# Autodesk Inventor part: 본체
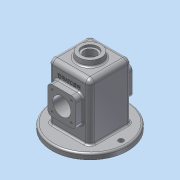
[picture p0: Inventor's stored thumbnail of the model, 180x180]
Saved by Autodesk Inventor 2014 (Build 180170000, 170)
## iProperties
Created: 2021-08
Part Number: 본체
Material: 알루미늄 6061
Document SubType Name: Modeling
Designer: dg
Density: 2.71 g/cm^3
Appearance: 알루미늄 - 평지
Mass: 823.388 g
Surface Area: 950.132 cm^2
Volume: 303.833 cm^3
Author: dg
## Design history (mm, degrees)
sketch "스케치1"
  geometry: L1 (37, -37)-(-37, -37); L2 (-37, -37)-(-37, 37); L3 (-37, 37)-(37, 37); L4 (37, 37)-(37, -37); L5 (37, -37)-(-37, 37); L6 (-37, -37)-(37, 37); 1 further point
  constraints: 12 end point, 2 midpoint, 2 parallel, 1 horizontal, 1 perpendicular
  dimensions: "d0" = 74 distance of L2.end L3.end; "d1" = 74 distance of L3.end L1.start
extrude "돌출1" new body sketch "스케치1" stored distance "d2" = 100; taper "d3" = 0 deg
node "작업 평면1"
sketch "스케치2"
  geometry: C1 r 67 at (0, 0); 1 further point
  constraints: 1 centre point, 1 coincident
  dimensions: "d5" = 134 diameter of C1
extrude "돌출2" join sketch "스케치2" distance "d6" = 10; taper "d7" = 0 deg
sketch "스케치3" dims "d8" = 110
  geometry: L1 (37, -37)-(-37, -37) reference; L2 (0, 0)-(0, 55); C1 r 67 at (0, 0) reference; C2 r 4.5 at (0, 55)
  constraints: 2 coincident, 2 end point, 1 centre point, 1 perpendicular, 1 vertical alignment, 2 other
  dimensions: "d9" = 9 diameter of C2
extrude "돌출3" cut sketch "스케치3" stored distance "d10" = 10; taper "d11" = 0 deg
fillet "모깎기1" dims "d12" = 3
fillet "모깎기2" dims "d13" = 8
sketch "스케치4"
  geometry: C1 r 20 at (0, 0); 1 further point
  constraints: 1 centre point, 1 coincident
  dimensions: "d14" = 40 diameter of C1
extrude "돌출4" join sketch "스케치4" distance "d15" = 10; taper "d16" = 0 deg
sketch "스케치5"
  geometry: L1 (-32, -32)-(32, -32); L2 (32, -32)-(32, 32); L3 (32, 32)-(-32, 32); L4 (-32, 32)-(-32, -32); L5 (-32, -32)-(32, 32); L6 (32, -32)-(-32, 32); C1 r 67 at (0, 0) reference
  constraints: 12 end point, 2 midpoint, 2 parallel, 1 horizontal, 1 perpendicular
  dimensions: "d17" = 64 distance of L2.end L3.end; "d18" = 64 distance of L1.end L2.end
extrude "돌출5" cut sketch "스케치5" distance "d19" = 105; taper "d20" = 0 deg
sketch "스케치6"
  geometry: C1 r 20 at (0, 0) reference; C2 r 14 at (0, 0)
  constraints: 1 centre point, 1 coincident
  dimensions: "d22" = 28 diameter of C2
extrude "돌출6" cut sketch "스케치6" distance "d23" = 4; taper "d24" = 0 deg
sketch "스케치7"
  geometry: C1 r 14 at (0, 0) reference; C2 r 10.5 at (0, 0)
  constraints: 1 centre point, 1 coincident
  dimensions: "d25" = 21 diameter of C2
extrude "돌출7" cut sketch "스케치7" stored distance "d26" = 4; taper "d27" = 0 deg
sketch "스케치8"
  geometry: L1 (67, 54)-(17, 54); L2 (17, 54)-(17, 4); L3 (17, 4)-(67, 4); L4 (67, 4)-(67, 54); L5 (67, 54)-(17, 4); L6 (17, 54)-(67, 4); 1 further point
  constraints: 12 end point, 2 midpoint, 2 parallel, 1 horizontal, 1 perpendicular
  dimensions: "d29" = 50 distance of L1.end L2.end; "d30" = 50 distance of L1.start L1.end
extrude "돌출8" join sketch "스케치8" distance "d31" = 13; taper "d32" = 0 deg
sketch "스케치9"
  geometry: C1 r 16 at (42, 29); 1 further point
  constraints: 1 centre point, 1 coincident
  dimensions: "d33" = 32 diameter of C1
extrude "돌출9" cut sketch "스케치9" stored distance "d34" = 13; taper "d35" = 0 deg
fillet "모깎기5" dims "d36" = 8
fillet "모깎기6" dims "d37" = 3
sketch "스케치10"
  geometry: L1 (59, 12)-(25, 12); L2 (25, 12)-(25, 46); L3 (25, 46)-(59, 46); L4 (59, 46)-(59, 12); L5 (59, 12)-(25, 46); L6 (25, 12)-(59, 46); C1 r 16 at (42, 29) reference; 1 further point
  constraints: 12 end point, 2 midpoint, 2 parallel, 1 coincident, 1 horizontal, 1 perpendicular
  dimensions: "d38" = 34 distance of L1.end L2.end; "d39" = 34 distance of L2.end L3.end
hole "구멍1" sketch "스케치10" at (25, 12) diameter "d40" = 3.242; stored, may be unused: countersink angle "d44" = 90 deg, drill point angle "d46" = 118 deg; dims "d41" = 8, "d42" = 4, "d43" = 2, "d45" = 10
sketch "스케치11"
  geometry: L1 (-32, -60)-(-32, 45) reference; L2 (-50, -16)-(-50, 16) reference; L3 (0, 0)-(-50, 0); L4 (-32, -25)-(-25, -22.452); L5 (-25, -22.452)-(-25, -16); L6 (-50, -16)-(-32, -16) reference; L7 (-25, -16)-(-32, -16)
  constraints: 8 end point, 1 collinear, 1 midpoint, 1 perpendicular, 1 point on line
  dimensions: "d53" = 110 deg angle of L1 L4; "d54" = 7 distance between parallel lines of L1 L5; "d55" = 50 diameter of L4.start L3
revolve "회전1" sketch "스케치11" stored, may be unused: angle "d56" = 90 deg
fillet "모깎기7" dims "d57" = 3
fillet "모깎기8" dims "d58" = 3
sketch "스케치12"
  geometry: L1 (-18, 49)-(-18, 9) reference; 2 further points
  constraints: 1 horizontal alignment, 1 other
  dimensions: "d59" = 28 distance from line of point (10, 29) L1
extrude "돌출10" join sketch "스케치12" distance "d60" = 0.5; taper "d61" = 0 deg
sketch "스케치13"
  geometry: L1 (-29, 50)-(29, 50) reference; L2 (37, 42)-(37, -47) reference; L3 (20, 50)-(20, 60) reference; L4 (20, 60)-(-20, 60) reference; L5 (20, 60)-(21.051, 50); L6 (0, 60)-(0, 0); L7 (21.051, 50)-(20, 50); L8 (20, 60)-(20, 50); A1 r 8 centre (29, 42) between (37, 42) and (29, 50) reference
  constraints: 8 end point, 3 perpendicular, 2 point on line, 1 midpoint
  dimensions: "d62" = 6 deg angle of L5 L2
revolve "회전2" sketch "스케치13" stored, may be unused: angle "d63" = 90 deg
fillet "모깎기9" dims "d64" = 3
node "솔리드1"
mirror "대칭1"
pattern_linear "직사각형 패턴1" dims "d49" = 34, "d52" = 34
mirror "대칭2"
